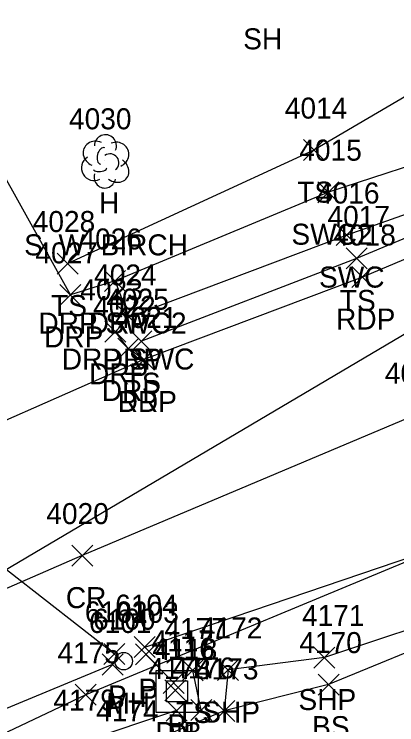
# Model space of a CAD drawing. Extents: x 1653135 to 1655489, y 602711 to 605684.
# Drawn here: x 1653512.2 to 1653548.7, y 605109.6 to 605177.2 of the extents above; entities that cross this region are included whole.
import ezdxf

# ---------------------------------------------------------------- set-up
doc = ezdxf.new("R2010")
doc.units = 0
for name, color, linetype in [('D_A', 7, 'Continuous'), ('D_I', 7, 'Continuous'), ('D_TIC', 7, 'Continuous'), ('DCP', 7, 'Continuous'), ('DS', 7, 'Continuous'), ('L_A', 7, 'Continuous'), ('L_C', 7, 'Continuous'), ('L_I', 7, 'Continuous'), ('L_TIC', 7, 'Continuous'), ('LELB', 7, 'Continuous'), ('LTD', 7, 'Continuous'), ('P_A', 7, 'Continuous'), ('P_I', 7, 'Continuous'), ('P_TIC', 7, 'Continuous'), ('PET', 7, 'Continuous'), ('PRC', 7, 'Continuous'), ('PSP', 7, 'Continuous'), ('R_A', 7, 'Continuous'), ('R_I', 7, 'Continuous'), ('R_TIC', 7, 'Continuous'), ('RDP', 7, 'Continuous'), ('RSW', 7, 'Continuous'), ('U_A', 7, 'Continuous'), ('U_I', 7, 'Continuous'), ('USA', 7, 'Continuous'), ('UUMH', 7, 'Continuous')]:
    doc.layers.add(name, color=color, linetype=linetype)

msp = doc.modelspace()

# ---------------------------------------------------------------- linework, layer by layer
at = {"layer": 'D_TIC'}
for points in [[(1653523.673, 605115.958), (1653525.673, 605117.958)], [(1653525.673, 605115.958), (1653523.673, 605117.958)], [(1653523.673, 605115.958), (1653525.673, 605117.958)], [(1653525.673, 605115.958), (1653523.673, 605117.958)], [(1653520.786, 605115.308), (1653522.786, 605117.308)], [(1653522.786, 605115.308), (1653520.786, 605117.308)], [(1653520.786, 605115.308), (1653522.786, 605117.308)], [(1653522.786, 605115.308), (1653520.786, 605117.308)], [(1653523.786, 605115.268), (1653525.786, 605117.268)], [(1653525.786, 605115.268), (1653523.786, 605117.268)], [(1653523.786, 605115.268), (1653525.786, 605117.268)], [(1653525.786, 605115.268), (1653523.786, 605117.268)], [(1653520.612, 605114.304), (1653522.612, 605116.304)], [(1653522.612, 605114.304), (1653520.612, 605116.304)], [(1653520.612, 605114.304), (1653522.612, 605116.304)], [(1653522.612, 605114.304), (1653520.612, 605116.304)], [(1653526.434, 605112.559), (1653528.434, 605114.559)], [(1653528.434, 605112.559), (1653526.434, 605114.559)], [(1653526.434, 605112.559), (1653528.434, 605114.559)], [(1653528.434, 605112.559), (1653526.434, 605114.559)], [(1653526.572, 605111.837), (1653528.572, 605113.837)], [(1653528.572, 605111.837), (1653526.572, 605113.837)], [(1653526.572, 605111.837), (1653528.572, 605113.837)], [(1653528.572, 605111.837), (1653526.572, 605113.837)]]:
    msp.add_lwpolyline(points, dxfattribs=at)
at = {"layer": 'DCP'}
for points in [[(1653524.673, 605116.958), (1653653.456, 605160.649)], [(1653498.418, 605134.542), (1653521.786, 605116.308)], [(1653527.434, 605113.559), (1653524.786, 605116.268)], [(1653521.612, 605115.304), (1653423.795, 605074.739)]]:
    msp.add_lwpolyline(points, dxfattribs=at)
at = {"layer": 'DS'}
for p, q in [((1653525.755, 605114.742), (1653529.755, 605114.742)), ((1653525.755, 605110.742), (1653525.755, 605114.742)), ((1653529.755, 605114.742), (1653529.755, 605110.742)), ((1653526.755, 605111.742), (1653526.755, 605113.742)), ((1653526.755, 605113.742), (1653528.755, 605113.742)), ((1653528.755, 605113.742), (1653528.755, 605111.742)), ((1653527.76, 605112.744), (1653527.76, 605112.744)), ((1653527.76, 605112.744), (1653527.76, 605112.744)), ((1653528.755, 605111.742), (1653526.755, 605111.742)), ((1653529.755, 605110.742), (1653525.755, 605110.742))]:
    msp.add_line(p, q, dxfattribs=at)
at = {"layer": 'L_TIC'}
for points in [[(1653539.781, 605163.268), (1653541.781, 605165.268)], [(1653541.781, 605163.268), (1653539.781, 605165.268)], [(1653539.781, 605163.268), (1653541.781, 605165.268)], [(1653541.781, 605163.268), (1653539.781, 605165.268)], [(1653543.843, 605152.96), (1653545.843, 605154.96)], [(1653545.843, 605152.96), (1653543.843, 605154.96)], [(1653543.843, 605152.96), (1653545.843, 605154.96)], [(1653545.843, 605152.96), (1653543.843, 605154.96)], [(1653516.34, 605152.471), (1653518.34, 605154.471)], [(1653518.34, 605152.471), (1653516.34, 605154.471)], [(1653516.34, 605152.471), (1653518.34, 605154.471)], [(1653518.34, 605152.471), (1653516.34, 605154.471)], [(1653523.349, 605145.079), (1653525.349, 605147.079)], [(1653525.349, 605145.079), (1653523.349, 605147.079)], [(1653523.349, 605145.079), (1653525.349, 605147.079)], [(1653525.349, 605145.079), (1653523.349, 605147.079)], [(1653528.242, 605113.734), (1653530.242, 605115.734)], [(1653530.242, 605113.734), (1653528.242, 605115.734)], [(1653528.242, 605113.734), (1653530.242, 605115.734)], [(1653530.242, 605113.734), (1653528.242, 605115.734)], [(1653541.174, 605112.389), (1653543.174, 605114.389)], [(1653543.174, 605112.389), (1653541.174, 605114.389)], [(1653541.174, 605112.389), (1653543.174, 605114.389)], [(1653543.174, 605112.389), (1653541.174, 605114.389)], [(1653526.694, 605109.916), (1653528.694, 605111.916)], [(1653528.694, 605109.916), (1653526.694, 605111.916)], [(1653526.694, 605109.916), (1653528.694, 605111.916)], [(1653528.694, 605109.916), (1653526.694, 605111.916)], [(1653529.05, 605109.972), (1653531.05, 605111.972)], [(1653531.05, 605109.972), (1653529.05, 605111.972)], [(1653529.05, 605109.972), (1653531.05, 605111.972)], [(1653531.05, 605109.972), (1653529.05, 605111.972)], [(1653531.247, 605109.88), (1653533.247, 605111.88)], [(1653533.247, 605109.88), (1653531.247, 605111.88)], [(1653531.247, 605109.88), (1653533.247, 605111.88)], [(1653533.247, 605109.88), (1653531.247, 605111.88)]]:
    msp.add_lwpolyline(points, dxfattribs=at)
at = {"layer": 'LELB'}
for points in [[(1653561.742, 605176.548), (1653540.781, 605164.268), (1653517.34, 605153.471)], [(1653569.041, 605164.05), (1653544.843, 605153.96), (1653524.349, 605146.079)], [(1653579.638, 605125.888), (1653554.405, 605118.421), (1653542.174, 605113.389), (1653532.247, 605110.88)], [(1653530.05, 605110.972), (1653529.242, 605114.734)], [(1653527.694, 605110.916), (1653518.669, 605107.92), (1653504.682, 605104.06)]]:
    msp.add_lwpolyline(points, dxfattribs=at)
at = {"layer": 'LTD'}
msp.add_line((1653520.882, 605163.249), (1653520.882, 605163.249), dxfattribs=at)
msp.add_line((1653520.882, 605163.249), (1653520.882, 605163.249), dxfattribs=at)
msp.add_arc((1653520.929, 605164.683), 1.047, 335.52715, 180.95627, dxfattribs=at)
for centre, major_axis, ratio, start_param, end_param in [((1653520.09, 605163.915), (1.21, -0.512), 0.895232, 1.570796, 4.712389), ((1653521.924, 605163.832), (-1.141, -0.483), 0.949671, 1.570796, 4.712389), ((1653520.674, 605163.707), (-0.208, -0.792), 0.645439, 3.141593, 6.283185), ((1653519.799, 605162.54), (0.584, -1.042), 0.959034, 3.141593, 6.283185), ((1653521.382, 605163.082), (-0.5, 0.667), 0.989748, 3.141593, 6.283185), ((1653521.882, 605162.416), (-1.09, 0.792), 0.841452, 1.570796, 4.712389), ((1653520.424, 605162.499), (-0.625, -0.083), 0.423636, 0, 3.141593), ((1653520.882, 605161.749), (0.265, 1.061), 0.942809, 1.570796, 4.712389)]:
    msp.add_ellipse(centre, major_axis=major_axis, ratio=ratio, start_param=start_param, end_param=end_param, dxfattribs=at)
at = {"layer": 'P_TIC'}
for points in [[(1653544.403, 605151.188), (1653546.403, 605153.188)], [(1653546.403, 605151.188), (1653544.403, 605153.188)], [(1653544.403, 605151.188), (1653546.403, 605153.188)], [(1653546.403, 605151.188), (1653544.403, 605153.188)], [(1653523.597, 605143.335), (1653525.597, 605145.335)], [(1653525.597, 605143.335), (1653523.597, 605145.335)], [(1653523.597, 605143.335), (1653525.597, 605145.335)], [(1653525.597, 605143.335), (1653523.597, 605145.335)], [(1653517.724, 605124.668), (1653519.724, 605126.668)], [(1653519.724, 605124.668), (1653517.724, 605126.668)], [(1653517.724, 605124.668), (1653519.724, 605126.668)], [(1653519.724, 605124.668), (1653517.724, 605126.668)], [(1653540.776, 605114.966), (1653542.776, 605116.966)], [(1653542.776, 605114.966), (1653540.776, 605116.966)], [(1653540.776, 605114.966), (1653542.776, 605116.966)], [(1653542.776, 605114.966), (1653540.776, 605116.966)], [(1653531.613, 605113.781), (1653533.613, 605115.781)], [(1653533.613, 605113.781), (1653531.613, 605115.781)], [(1653531.613, 605113.781), (1653533.613, 605115.781)], [(1653533.613, 605113.781), (1653531.613, 605115.781)], [(1653518.051, 605111.425), (1653520.051, 605113.425)], [(1653520.051, 605111.425), (1653518.051, 605113.425)], [(1653518.051, 605111.425), (1653520.051, 605113.425)], [(1653520.051, 605111.425), (1653518.051, 605113.425)], [(1653531.247, 605109.88), (1653533.247, 605111.88)], [(1653533.247, 605109.88), (1653531.247, 605111.88)], [(1653531.247, 605109.88), (1653533.247, 605111.88)], [(1653533.247, 605109.88), (1653531.247, 605111.88)]]:
    msp.add_lwpolyline(points, dxfattribs=at)
at = {"layer": 'PET'}
for points in [[(1653570.485, 605162.786), (1653545.403, 605152.188), (1653524.597, 605144.335), (1653501.66, 605134.239), (1653492.53, 605129.6), (1653483.217, 605126.16), (1653461.507, 605114.196), (1653431.751, 605097.051), (1653402.439, 605074.196), (1653383.496, 605058.488), (1653369.863, 605045.734), (1653350.113, 605021.59), (1653336.009, 605007.549), (1653322.852, 604993.824), (1653302.166, 604970.774), (1653290.93, 604958.375), (1653272.167, 604938.098), (1653250.651, 604913.142), (1653232.406, 604892.896), (1653208.357, 604866.317), (1653177.81, 604831.245), (1653160.535, 604811.983)], [(1653576.316, 605135.262), (1653553.767, 605126.837), (1653519.051, 605112.425), (1653493.535, 605100.339), (1653468.833, 605088.005), (1653447.853, 605075.02), (1653427.596, 605061.865), (1653406.781, 605044.605), (1653388.905, 605027.698), (1653366.499, 605004.888), (1653354.584, 604992.023), (1653334.896, 604970.66), (1653318.046, 604952.193), (1653296.488, 604928.187), (1653274.624, 604903.556), (1653244.239, 604868.756), (1653225.75, 604847.701), (1653206.334, 604825.65), (1653179.645, 604794.747)]]:
    msp.add_lwpolyline(points, dxfattribs=at)
at = {"layer": 'PRC'}
msp.add_lwpolyline([(1653576.361, 605149.524), (1653550.317, 605139.021), (1653518.724, 605125.668), (1653498.017, 605116.666), (1653468.035, 605101.489), (1653440.124, 605084.852), (1653411.973, 605063.454), (1653392.179, 605045.924), (1653380.925, 605035.31), (1653360.25, 605013.969), (1653332.49, 604984.793), (1653311.146, 604961.542), (1653300.12, 604949.228), (1653281.614, 604928.677), (1653260.957, 604905.277), (1653242.089, 604884.435), (1653216.566, 604855.116), (1653187.493, 604822.135), (1653170.081, 604802.31)], dxfattribs=at)
at = {"layer": 'PSP'}
msp.add_lwpolyline([(1653577.495, 605132.222), (1653555.735, 605120.61), (1653541.776, 605115.966), (1653532.613, 605114.781), (1653532.247, 605110.88), (1653522.733, 605106.898), (1653507.697, 605103.522), (1653493.111, 605096.605), (1653471.403, 605083.027), (1653450.958, 605070.25), (1653430.837, 605057.523), (1653410.321, 605040.006), (1653392.797, 605023.713), (1653372.132, 605001.835), (1653359.179, 604987.803), (1653339.003, 604967.206), (1653322.133, 604948.589), (1653300.744, 604925.192), (1653278.521, 604900.611), (1653247.528, 604865.908), (1653229.566, 604844.432), (1653209.3, 604822.581), (1653182.433, 604791.771)], dxfattribs=at)
at = {"layer": 'R_TIC'}
for points in [[(1653541.166, 605159.262), (1653543.166, 605161.262)], [(1653543.166, 605159.262), (1653541.166, 605161.262)], [(1653541.166, 605159.262), (1653543.166, 605161.262)], [(1653543.166, 605159.262), (1653541.166, 605161.262)], [(1653542.905, 605155.182), (1653544.905, 605157.182)], [(1653544.905, 605155.182), (1653542.905, 605157.182)], [(1653542.905, 605155.182), (1653544.905, 605157.182)], [(1653544.905, 605155.182), (1653542.905, 605157.182)], [(1653520.845, 605150.81), (1653522.845, 605152.81)], [(1653522.845, 605150.81), (1653520.845, 605152.81)], [(1653520.845, 605150.81), (1653522.845, 605152.81)], [(1653522.845, 605150.81), (1653520.845, 605152.81)], [(1653520.845, 605150.81), (1653522.845, 605152.81)], [(1653522.845, 605150.81), (1653520.845, 605152.81)], [(1653520.845, 605150.81), (1653522.845, 605152.81)], [(1653522.845, 605150.81), (1653520.845, 605152.81)], [(1653516.595, 605149.486), (1653518.595, 605151.486)], [(1653518.595, 605149.486), (1653516.595, 605151.486)], [(1653516.595, 605149.486), (1653518.595, 605151.486)], [(1653518.595, 605149.486), (1653516.595, 605151.486)], [(1653522.185, 605147.382), (1653524.185, 605149.382)], [(1653524.185, 605147.382), (1653522.185, 605149.382)], [(1653522.185, 605147.382), (1653524.185, 605149.382)], [(1653524.185, 605147.382), (1653522.185, 605149.382)], [(1653522.185, 605147.382), (1653524.185, 605149.382)], [(1653524.185, 605147.382), (1653522.185, 605149.382)], [(1653522.185, 605147.382), (1653524.185, 605149.382)], [(1653524.185, 605147.382), (1653522.185, 605149.382)], [(1653520.869, 605145.98), (1653522.869, 605147.98)], [(1653522.869, 605145.98), (1653520.869, 605147.98)], [(1653520.869, 605145.98), (1653522.869, 605147.98)], [(1653522.869, 605145.98), (1653520.869, 605147.98)], [(1653522.093, 605144.382), (1653524.093, 605146.382)], [(1653524.093, 605144.382), (1653522.093, 605146.382)], [(1653522.093, 605144.382), (1653524.093, 605146.382)], [(1653524.093, 605144.382), (1653522.093, 605146.382)], [(1653523.597, 605143.335), (1653525.597, 605145.335)], [(1653525.597, 605143.335), (1653523.597, 605145.335)], [(1653523.597, 605143.335), (1653525.597, 605145.335)], [(1653525.597, 605143.335), (1653523.597, 605145.335)]]:
    msp.add_lwpolyline(points, dxfattribs=at)
at = {"layer": 'RDP'}
msp.add_lwpolyline([(1653524.597, 605144.335), (1653523.093, 605145.382), (1653521.869, 605146.98), (1653523.185, 605148.382), (1653521.845, 605151.81), (1653517.595, 605150.486), (1653508.482, 605166.812)], dxfattribs=at)
at = {"layer": 'RSW'}
for points in [[(1653567.138, 605168.381), (1653542.166, 605160.262), (1653521.845, 605151.81)], [(1653568.702, 605164.918), (1653543.905, 605156.182), (1653523.185, 605148.382)]]:
    msp.add_lwpolyline(points, dxfattribs=at)
at = {"layer": 'USA'}
msp.add_lwpolyline([(1653424.094, 605072.763), (1653667.014, 605216.275)], dxfattribs=at)
at = {"layer": 'UUMH'}
for p, q in [((1653522.657, 605115.616), (1653522.657, 605115.616)), ((1653523.49, 605115.616), (1653523.49, 605115.616))]:
    msp.add_line(p, q, dxfattribs=at)
msp.add_circle((1653522.657, 605115.616), 0.833, dxfattribs=at)

# ---------------------------------------------------------------- texts
at = {"layer": 'D_A'}
for s, p in [('P', (1653524.051, 605111.958)), ('P', (1653524.051, 605111.958)), ('P', (1653521.164, 605111.308)), ('P', (1653521.164, 605111.308)), ('P', (1653524.164, 605111.268)), ('P', (1653524.164, 605111.268)), ('P', (1653520.99, 605110.304)), ('P', (1653520.99, 605110.304)), ('P', (1653526.812, 605108.559)), ('P', (1653526.812, 605108.559)), ('DIB', (1653525.675, 605107.837)), ('DIB', (1653525.675, 605107.837)), ('DI', (1653526.815, 605107.744))]:
    msp.add_text(s, height=2, dxfattribs=at).set_placement(p)
at = {"layer": 'D_I'}
for s, p in [('6104', (1653521.854, 605119.958)), ('6104', (1653521.854, 605119.958)), ('6102', (1653518.967, 605119.308)), ('6102', (1653518.967, 605119.308)), ('6103', (1653521.967, 605119.268)), ('6103', (1653521.967, 605119.268)), ('6101', (1653519.36, 605118.304)), ('6101', (1653519.36, 605118.304)), ('4117', (1653525.309, 605116.559)), ('4117', (1653525.309, 605116.559)), ('4116', (1653525.392, 605115.837)), ('4116', (1653525.392, 605115.837)), ('4118', (1653525.635, 605115.744))]:
    msp.add_text(s, height=2, dxfattribs=at).set_placement(p)
at = {"layer": 'L_A'}
for s, p in [('SH', (1653534.044, 605173.862)), ('SH', (1653534.044, 605173.862)), ('TS', (1653539.191, 605159.268)), ('TS', (1653539.191, 605159.268)), ('H', (1653520.315, 605158.249)), ('TS', (1653543.252, 605148.96)), ('TS', (1653543.252, 605148.96)), ('TS', (1653515.75, 605148.471)), ('TS', (1653515.75, 605148.471)), ('TS', (1653522.759, 605141.079)), ('TS', (1653522.759, 605141.079)), ('TS', (1653527.652, 605109.734)), ('TS', (1653527.652, 605109.734)), ('BS', (1653540.615, 605108.389)), ('BS', (1653540.615, 605108.389))]:
    msp.add_text(s, height=2, dxfattribs=at).set_placement(p)
at = {"layer": 'L_C'}
msp.add_text('S. W. BIRCH', height=2, dxfattribs=at).set_placement((1653513.181, 605154.249))
at = {"layer": 'L_I'}
for s, p in [('4014', (1653538.01, 605167.268)), ('4014', (1653538.01, 605167.268)), ('4030', (1653517.457, 605166.249)), ('4017', (1653542.071, 605156.96)), ('4017', (1653542.071, 605156.96)), ('4028', (1653514.002, 605156.471)), ('4028', (1653514.002, 605156.471)), ('4025', (1653521.011, 605149.079)), ('4025', (1653521.011, 605149.079)), ('4177', (1653526.549, 605117.734)), ('4177', (1653526.549, 605117.734)), ('4170', (1653539.394, 605116.389)), ('4170', (1653539.394, 605116.389)), ('4178', (1653525.001, 605113.916)), ('4178', (1653525.001, 605113.916)), ('4176', (1653527.303, 605113.972)), ('4176', (1653527.303, 605113.972)), ('4173', (1653529.554, 605113.88)), ('4173', (1653529.554, 605113.88)), ('4179', (1653515.968, 605110.92)), ('4179', (1653515.968, 605110.92))]:
    msp.add_text(s, height=2, dxfattribs=at).set_placement(p)
at = {"layer": 'P_A'}
for s, p in [('RDP', (1653542.891, 605147.188)), ('RDP', (1653542.891, 605147.188)), ('RDP', (1653522.085, 605139.335)), ('RDP', (1653522.085, 605139.335)), ('CR', (1653517.157, 605120.668)), ('CR', (1653517.157, 605120.668)), ('SHP', (1653539.311, 605110.966)), ('SHP', (1653539.311, 605110.966)), ('SHP', (1653530.149, 605109.781)), ('SHP', (1653530.149, 605109.781))]:
    msp.add_text(s, height=2, dxfattribs=at).set_placement(p)
at = {"layer": 'P_I'}
for s, p in [('4018', (1653542.631, 605155.188)), ('4018', (1653542.631, 605155.188)), ('4021', (1653521.826, 605147.335)), ('4021', (1653521.826, 605147.335)), ('4019', (1653547.538, 605142.021)), ('4019', (1653547.538, 605142.021)), ('4020', (1653515.299, 605128.668)), ('4020', (1653515.299, 605128.668)), ('4171', (1653539.65, 605118.966)), ('4171', (1653539.65, 605118.966)), ('4172', (1653529.92, 605117.781)), ('4172', (1653529.92, 605117.781)), ('4175', (1653516.358, 605115.425)), ('4175', (1653516.358, 605115.425)), ('4173', (1653529.554, 605113.88)), ('4173', (1653529.554, 605113.88)), ('4174', (1653520.04, 605109.898)), ('4174', (1653520.04, 605109.898))]:
    msp.add_text(s, height=2, dxfattribs=at).set_placement(p)
at = {"layer": 'R_A'}
for s, p in [('SWC2', (1653538.638, 605155.262)), ('SWC2', (1653538.638, 605155.262)), ('SWC', (1653541.268, 605151.182)), ('SWC', (1653541.268, 605151.182)), ('DRP SWC2', (1653514.538, 605146.81)), ('DRP SWC2', (1653514.538, 605146.81)), ('DRP', (1653519.333, 605146.81)), ('DRP', (1653519.333, 605146.81)), ('DRP', (1653515.083, 605145.486)), ('DRP', (1653515.083, 605145.486)), ('DRP SWC', (1653516.767, 605143.382)), ('DRP SWC', (1653516.767, 605143.382)), ('DRP', (1653520.673, 605143.382)), ('DRP', (1653520.673, 605143.382)), ('DRP', (1653519.357, 605141.98)), ('DRP', (1653519.357, 605141.98)), ('DRP', (1653520.581, 605140.382)), ('DRP', (1653520.581, 605140.382)), ('DRP', (1653522.085, 605139.335)), ('DRP', (1653522.085, 605139.335))]:
    msp.add_text(s, height=2, dxfattribs=at).set_placement(p)
at = {"layer": 'R_I'}
for s, p in [('4015', (1653539.394, 605163.262)), ('4015', (1653539.394, 605163.262)), ('4016', (1653541.079, 605159.182)), ('4016', (1653541.079, 605159.182)), ('4026', (1653518.452, 605154.81)), ('4026', (1653518.452, 605154.81)), ('4026', (1653518.452, 605154.81)), ('4026', (1653518.452, 605154.81)), ('4027', (1653514.256, 605153.486)), ('4027', (1653514.256, 605153.486)), ('4024', (1653519.846, 605151.382)), ('4024', (1653519.846, 605151.382)), ('4024', (1653519.846, 605151.382)), ('4024', (1653519.846, 605151.382)), ('4023', (1653518.53, 605149.98)), ('4023', (1653518.53, 605149.98)), ('4022', (1653519.755, 605148.382)), ('4022', (1653519.755, 605148.382)), ('4021', (1653521.826, 605147.335)), ('4021', (1653521.826, 605147.335))]:
    msp.add_text(s, height=2, dxfattribs=at).set_placement(p)
at = {"layer": 'U_A'}
msp.add_text('MH', height=2, dxfattribs=at).set_placement((1653521.019, 605110.616))
at = {"layer": 'U_I'}
msp.add_text('6100', height=2, dxfattribs=at).set_placement((1653519.752, 605118.616))

doc.saveas('drawing.dxf')
